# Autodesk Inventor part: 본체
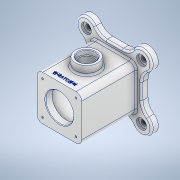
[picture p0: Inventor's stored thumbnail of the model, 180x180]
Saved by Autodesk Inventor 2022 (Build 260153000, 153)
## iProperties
Created: 2022-05
Part Number: 본체
Material: 알루미늄 6061
Document SubType Name: Modeling
Designer: admin
Mass: 1072.03 g
Surface Area: 882.476 cm^2
Volume: 397.049 cm^3
Density: 2.7 g/cm^3
Appearance: 알루미늄 - 평지
Author: admin
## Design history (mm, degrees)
sketch "스케치1" dims "d2" = 140
  geometry: L1 (-49, -49)-(49, -49); L2 (49, -49)-(49, 49); L3 (49, 49)-(-49, 49); L4 (-49, 49)-(-49, -49); L5 (-49, -49)-(49, 49); L6 (49, -49)-(-49, 49); L7 (49, 49)-(50.23, 50.23); L8 (0, -98.983)-(0, 103.897) reference; L9 (-100.773, 0)-(114.637, 0) reference; L10 (49.458, 74.914)-(24.842, 50.298); L11 (83.864, 58.408)-(54.491, 29.035); C1 r 18 at (49.497, 49.497); C2 r 18 at (49.497, 49.497); C3 r 18 at (-49.497, 49.497); C4 r 18 at (49.497, -49.497); C5 r 18 at (-49.497, -49.497); 10 further points
  constraints: 18 end point, 5 centre point, 3 symmetric about line, 2 coincident, 2 midpoint, 2 parallel, 2 tangent, 1 horizontal, 1 perpendicular, 1 point on line, 6 other
  dimensions: "d0" = 98 distance of L3.end L2.end; "d1" = 98 distance of L2.end L1.end; "d5" = 45 deg angle of L7 L3; "d6" = 36 diameter of C1; "d73" = 135 deg angle of L10 L3; "d74" = 45 deg angle of L3 L11
extrude "돌출1" new body sketch "스케치1" distance "d7" = 12; taper "d8" = 0 deg
fillet "모깎기1" dims "d9" = 25
sketch "스케치2"
  geometry: L1 (-40, -40)-(40, -40); L2 (40, -40)-(40, 40); L3 (40, 40)-(-40, 40); L4 (-40, 40)-(-40, -40); L5 (-40, -40)-(40, 40); L6 (40, -40)-(-40, 40); 1 further point
  constraints: 12 end point, 2 midpoint, 2 parallel, 1 horizontal, 1 perpendicular
  dimensions: "d10" = 80 distance of L3.end L2.end; "d11" = 80 distance of L1.end L2.end
extrude "돌출2" join sketch "스케치2" distance "d12" = 98; taper "d13" = 0 deg
sketch "스케치3"
  geometry: L1 (0, -22)-(0, 132) reference; L2 (40, 110)-(-40, 110) reference; L3 (0, 110)-(25, 110); L4 (25, 110)-(25, 98); L5 (25, 98)-(0, 98); L6 (0, 98)-(0, 110); L7 (0, 98)-(35, 98); L8 (35, 98)-(35, 12); L9 (35, 12)-(0, 12); L10 (0, 12)-(0, 98); L11 (0, 12)-(25, 12); L12 (25, 12)-(25, 0); L13 (25, 0)-(0, 0); L14 (0, 0)-(0, 12); 4 further points
  constraints: 24 end point, 6 parallel, 3 horizontal, 3 perpendicular, 1 midpoint
  dimensions: "d14" = 50 diameter of L12 L1; "d15" = 50 diameter of L4 L1; "d16" = 70 diameter of L8 L1; "d17" = 12 distance between parallel lines of L5 L2; "d18" = 86 distance between parallel lines of L11 L5; "d19" = 12 distance between parallel lines of L11 L13
revolve "회전1" sketch "스케치3" stored, may be unused: angle "d20" = 90 deg
node "작업 평면1"
sketch "스케치4"
  geometry: L1 (34.706, 12)-(14.162, 12) reference; L2 (0, -16.2)-(0, 97.2) reference; C1 r 20 at (0, 61); 1 further point
  constraints: 1 centre point, 1 point on line
  dimensions: "d22" = 40 diameter of C1; "d23" = 49 distance from line of C1.centre L1
extrude "돌출3" join sketch "스케치4" stored distance "d24" = 98; taper "d25" = 0 deg
sketch "스케치5"
  geometry: C1 r 20 at (0, 0) reference; C2 r 15 at (0, 0); 1 further point
  constraints: 1 centre point, 1 coincident
  dimensions: "d26" = 30 diameter of C2
extrude "돌출4" cut sketch "스케치5" distance "d27" = 8; taper "d28" = 0 deg
sketch "스케치6"
  geometry: C1 r 20 at (0, 0) reference; C2 r 12.5 at (0, 0); 1 further point
  constraints: 1 centre point, 1 coincident
  dimensions: "d29" = 25 diameter of C2
extrude "돌출5" cut sketch "스케치6" stored distance "d30" = 8; taper "d31" = 0 deg
sketch "스케치7"
  geometry: L1 (-30, -30)-(30, -30); L2 (30, -30)-(30, 30); L3 (30, 30)-(-30, 30); L4 (-30, 30)-(-30, -30); L5 (-30, -30)-(30, 30); L6 (30, -30)-(-30, 30); 5 further points
  constraints: 12 end point, 3 coincident, 2 midpoint, 2 parallel, 1 horizontal, 1 perpendicular, 1 point on line
  dimensions: "d32" = 60 distance of L3.end L2.end; "d33" = 60 distance of L1.end L2.end
hole "구멍1" sketch "스케치7" at (-30, 30), (30, 30), (-30, -30), (30, -30) diameter "d34" = 3.242; stored, may be unused: countersink angle "d38" = 90 deg, drill point angle "d40" = 118 deg; dims "d35" = 8, "d36" = 4, "d37" = 2, "d39" = 10
sketch "스케치8"
  geometry: L1 (-30, -30)-(30, -30); L2 (30, -30)-(30, 30); L3 (30, 30)-(-30, 30); L4 (-30, 30)-(-30, -30); L5 (-30, -30)-(30, 30); L6 (30, -30)-(-30, 30); C1 r 1.621 at (-30, 30) reference; C2 r 1.621 at (30, 30) reference; C3 r 1.621 at (30, -30) reference; C4 r 1.621 at (-30, -30) reference; 5 further points
  constraints: 12 end point, 4 coincident, 2 midpoint, 2 parallel, 1 horizontal, 1 perpendicular
  dimensions: "d41" = 60 distance of L3.end L2.end; "d42" = 60 distance of L2.end L1.end
hole "구멍2" sketch "스케치8" at (-30, 30), (30, 30), (30, -30), (-30, -30) diameter "d43" = 3.242; stored, may be unused: countersink angle "d47" = 90 deg, drill point angle "d49" = 118 deg; dims "d44" = 8, "d45" = 4, "d46" = 2, "d48" = 10
sketch "스케치9"
  geometry: A1 r 18 centre (-49.497, 49.497) between (-34.706, 59.754) and (-59.754, 34.706) reference; 2 further points
  constraints: 1 coincident
hole "구멍3" sketch "스케치9" at (-49.497, 49.497) diameter "d50" = 10; stored, may be unused: countersink angle "d54" = 90 deg, drill point angle "d56" = 118 deg; dims "d51" = 8, "d52" = 18, "d53" = 4, "d55" = 10
fillet "모깎기2" dims "d57" = 10
fillet "모깎기3" dims "d58" = 3
chamfer "모따기1" distance "d59" = 1; stored, may be unused: second distance "d60" = 2, angle "d61" = 45 deg
chamfer "모따기2" distance "d62" = 1; stored, may be unused: second distance "d63" = 2, angle "d64" = 45 deg
fillet "모깎기4" dims "d65" = 3
sketch "스케치10"
  geometry: L1 (30, 34)-(30, -120) reference; L2 (60, -98)-(0, -98) reference; 2 further points
  constraints: 1 point on line, 1 other
  dimensions: "d66" = 10 distance from line of point (30, -88) L2
feature "엠보싱1" sketch "스케치10" dims "d0" = 98, "d1" = 98, "d2" = 140, "d5" = 45 deg, "d6" = 36, "d67" = 0.5, "d68" = 0, "d73" = 135 deg, "d74" = 45 deg
chamfer "모따기3" distance "d69" = 1; stored, may be unused: second distance "d70" = 2, angle "d71" = 45 deg
fillet "모깎기5" dims "d72" = 3
node "솔리드1"
mirror "미러1"
mirror "미러2"
feature "A9D066F2-1C7D-4E18-AEED-F7BC21143FA4" dims "d50" = 10, "d51" = 8, "d52" = 18, "d53" = 4, "d54" = 90 deg, "d55" = 10, "d56" = 118 deg
other parameters: "d21" = 55
